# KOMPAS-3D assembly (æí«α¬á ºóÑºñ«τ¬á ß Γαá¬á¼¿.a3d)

Referenced files in D:\МОДЕЛЬ ТАНКА Т90\ДЕТАЛИ\ХОДОВАЯ\звездочка\: ведущая звездочка.m3d, диск звездочки.m3d, ведущая звездочка1.m3d, ось звездочки.m3d, крышка звездочки наружняя.m3d
Referenced files in D:\МОДЕЛЬ ТАНКА Т90\ДЕТАЛИ\ХОДОВАЯ\Каток опорный с балансиром\: шпилька соеденения катков.m3d
Referenced files in D:\МОДЕЛЬ ТАНКА Т90\ПОДСБОРКИ\ХОДОВАЯ\: Сборка трак мелкий.a3d
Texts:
  Сборка звездочка  с траками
